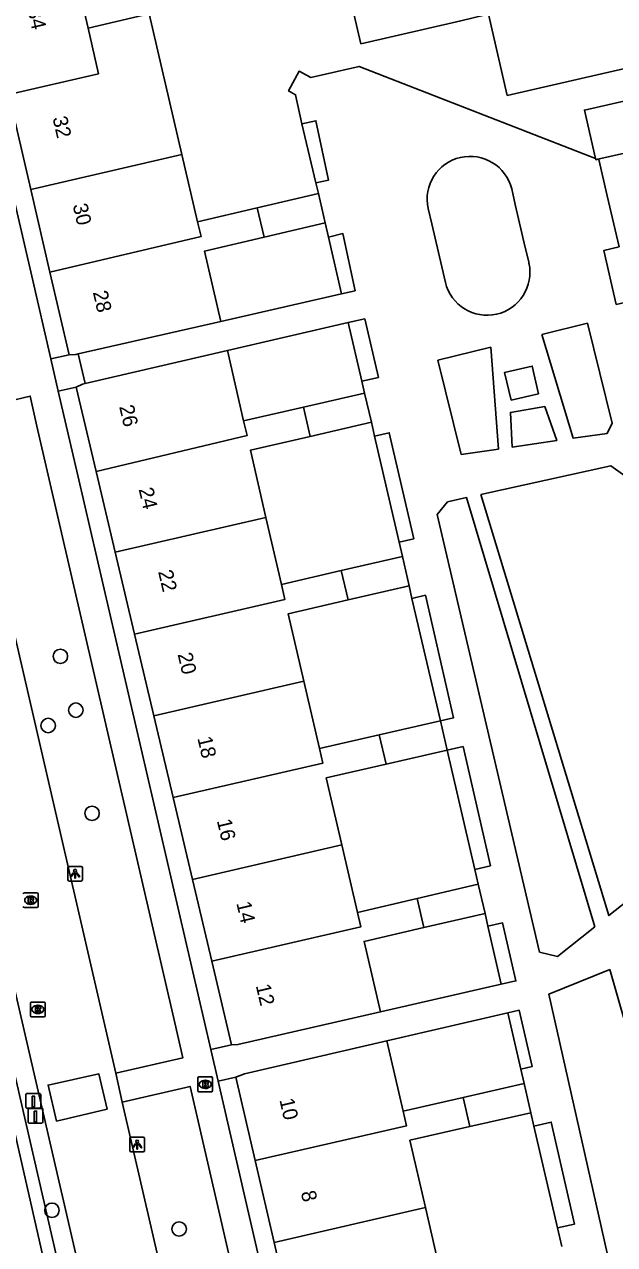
# Model space of a CAD drawing. Extents: x 156414 to 157775, y 382335 to 383765.
# Drawn here: x 156886.2 to 156926.2, y 383041 to 383123.7 of the extents above; entities that cross this region are included whole.
import ezdxf

# ---------------------------------------------------------------- set-up
doc = ezdxf.new("R2010")
doc.units = 0
for name, color, linetype in [('IMGEO_Berm_groen', 7, 'Continuous'), ('IMGEO_Boom', 7, 'Continuous'), ('IMGEO_Brandkraan', 7, 'Continuous'), ('IMGEO_Erf', 7, 'Continuous'), ('IMGEO_Greppel_droge_sloot', 7, 'Continuous'), ('IMGEO_Hek', 7, 'Continuous'), ('IMGEO_Lichtpunt', 7, 'Continuous'), ('IMGEO_Paal', 7, 'Continuous'), ('IMGEO_Pand', 7, 'Continuous'), ('IMGEO_Pand_nummerreeks', 7, 'Continuous'), ('IMGEO_Rijbaan_lokaal_gesloten', 7, 'Continuous'), ('IMGEO_Rijbaan_lokaal_open', 7, 'Continuous'), ('IMGEO_Rioolput', 7, 'Continuous'), ('IMGEO_Voetpad_open', 7, 'Continuous')]:
    doc.layers.add(name, color=color, linetype=linetype)

msp = doc.modelspace()

# ---------------------------------------------------------------- linework, layer by layer
at = {"layer": 'IMGEO_Berm_groen'}
msp.add_lwpolyline([(156881.029, 383072.193), (156889.957, 383033.371)], dxfattribs=at)
at = {"layer": 'IMGEO_Boom'}
for centre in [(156888.653, 383080.852), (156889.7, 383077.2), (156887.825, 383076.159), (156890.8, 383070.206), (156888.077, 383043.294), (156896.705, 383042.022)]:
    msp.add_circle(centre, 0.489, dxfattribs=at)
at = {"layer": 'IMGEO_Brandkraan'}
for p, q in [((156897.974, 383051.404), (156897.974, 383052.256)), ((156898.049, 383052.33), (156898.901, 383052.33)), ((156898.462, 383052.11), (156898.487, 383052.11)), ((156898.975, 383052.256), (156898.975, 383051.404)), ((156898.901, 383051.33), (156898.049, 383051.33)), ((156898.485, 383051.55), (156898.46, 383051.55))]:
    msp.add_line(p, q, dxfattribs=at)
for points in [[(156897.974, 383051.404), (156897.974, 383052.256)], [(156898.049, 383052.33), (156898.901, 383052.33)], [(156898.322, 383052.03), (156898.322, 383051.63), (156898.535, 383051.63)], [(156898.553, 383052.03), (156898.322, 383052.03)], [(156898.501, 383051.949), (156898.447, 383051.949), (156898.447, 383051.873)], [(156898.447, 383051.873), (156898.5, 383051.873)], [(156898.509, 383051.797), (156898.447, 383051.797), (156898.447, 383051.716)], [(156898.447, 383051.716), (156898.509, 383051.716)], [(156898.975, 383052.256), (156898.975, 383051.404)], [(156898.901, 383051.33), (156898.049, 383051.33)]]:
    msp.add_lwpolyline(points, dxfattribs=at)
for centre, radius, start, end in [((156898.051, 383052.254), 0.0765, 91.55205, 178.44795), ((156898.051, 383052.254), 0.0765, 91.55205, 178.44795), ((156898.502, 383051.911), 0.0379, 267.82845, 90.93552), ((156898.51, 383051.756), 0.0404, 269.87594, 90.50774), ((156898.541, 383051.881), 0.251, 268.66757, 293.53466), ((156898.557, 383051.885), 0.145, 59.4692, 91.53667), ((156898.582, 383051.932), 0.0922, 285.51372, 58.15012), ((156898.587, 383051.74), 0.105, 301.31148, 78.98903), ((156898.899, 383052.254), 0.0765, 1.55205, 88.44795), ((156898.899, 383052.254), 0.0765, 1.55205, 88.44795), ((156898.051, 383051.406), 0.0765, 181.55205, 268.44795), ((156898.051, 383051.406), 0.0765, 181.55205, 268.44795), ((156898.899, 383051.406), 0.0765, 271.55205, 358.44795), ((156898.899, 383051.406), 0.0765, 271.55205, 358.44795)]:
    msp.add_arc(centre, radius, start, end, dxfattribs=at)
for centre, major_axis, ratio, start_param, end_param in [((156898.461, 383051.83), (-0.387, 0.002), 0.722429, 4.712389, 7.853982), ((156898.486, 383051.83), (-0.39, 0.002), 0.717154, 1.570796, 4.712389)]:
    msp.add_ellipse(centre, major_axis=major_axis, ratio=ratio, start_param=start_param, end_param=end_param, dxfattribs=at)
at = {"layer": 'IMGEO_Erf'}
for points in [[(156905.981, 383112.959), (156905.026, 383116.964)], [(156907.714, 383105.431), (156906.834, 383109.282)], [(156908.172, 383103.475), (156909.093, 383099.499)], [(156909.964, 383095.778), (156911.622, 383088.598)], [(156912.494, 383084.782), (156914.423, 383076.479)], [(156914.882, 383074.49), (156916.748, 383066.407)], [(156918.547, 383058.619), (156917.645, 383062.552)], [(156919.88, 383052.856), (156918.997, 383056.674)], [(156922.363, 383042.091), (156920.759, 383049)]]:
    msp.add_lwpolyline(points, dxfattribs=at)
at = {"layer": 'IMGEO_Greppel_droge_sloot'}
msp.add_lwpolyline([(156888.996, 383033.414), (156881.195, 383067.66), (156880.531, 383071.202)], dxfattribs=at)
at = {"layer": 'IMGEO_Hek'}
msp.add_lwpolyline([(156890.338, 383099.343), (156889.863, 383101.352)], dxfattribs=at)
at = {"layer": 'IMGEO_Lichtpunt'}
for p, q in [((156889.153, 383066.516), (156889.153, 383065.709)), ((156889.153, 383066.516), (156889.153, 383065.709)), ((156890.055, 383066.611), (156889.247, 383066.611)), ((156890.055, 383066.611), (156889.247, 383066.611)), ((156890.149, 383065.709), (156890.149, 383066.516)), ((156890.149, 383065.709), (156890.149, 383066.516)), ((156889.247, 383065.615), (156890.055, 383065.615)), ((156889.247, 383065.615), (156890.055, 383065.615)), ((156893.361, 383048.152), (156893.361, 383047.345)), ((156893.361, 383048.152), (156893.361, 383047.345)), ((156894.263, 383048.247), (156893.455, 383048.247)), ((156894.263, 383048.247), (156893.455, 383048.247)), ((156894.357, 383047.345), (156894.357, 383048.152)), ((156894.357, 383047.345), (156894.357, 383048.152)), ((156893.455, 383047.251), (156894.263, 383047.251)), ((156893.455, 383047.251), (156894.263, 383047.251))]:
    msp.add_line(p, q, dxfattribs=at)
for points in [[(156889.527, 383066.18), (156889.566, 383066.152), (156889.378, 383065.89), (156889.34, 383065.917), (156889.527, 383066.18)], [(156889.629, 383066.132), (156889.676, 383066.132), (156889.676, 383065.81), (156889.629, 383065.81), (156889.629, 383066.132)], [(156889.739, 383066.152), (156889.777, 383066.179), (156889.964, 383065.917), (156889.925, 383065.889), (156889.739, 383066.152)], [(156893.735, 383047.816), (156893.774, 383047.788), (156893.586, 383047.526), (156893.548, 383047.553), (156893.735, 383047.816)], [(156893.837, 383047.768), (156893.884, 383047.768), (156893.884, 383047.446), (156893.837, 383047.446), (156893.837, 383047.768)], [(156893.947, 383047.788), (156893.985, 383047.815), (156894.172, 383047.553), (156894.133, 383047.525), (156893.947, 383047.788)]]:
    msp.add_lwpolyline(points, dxfattribs=at)
for centre in [(156889.652, 383066.314), (156893.86, 383047.95)]:
    msp.add_circle(centre, 0.0994, dxfattribs=at)
for centre, start, end in [((156889.247, 383066.516), 90, 180), ((156889.247, 383066.516), 90, 180), ((156890.055, 383066.516), 0, 90), ((156890.055, 383066.516), 0, 90), ((156889.247, 383065.709), 180, 270), ((156889.247, 383065.709), 180, 270), ((156890.055, 383065.709), 270, 0), ((156890.055, 383065.709), 270, 360), ((156893.455, 383048.152), 90, 180), ((156893.455, 383048.152), 90, 180), ((156894.263, 383048.152), 0, 90), ((156894.263, 383048.152), 0, 90), ((156893.455, 383047.345), 180, 270), ((156893.455, 383047.345), 180, 270), ((156894.263, 383047.345), 270, 0), ((156894.263, 383047.345), 270, 360)]:
    msp.add_arc(centre, 0.0946, start, end, dxfattribs=at)
at = {"layer": 'IMGEO_Paal'}
for p, q in [((156886.316, 383051.134), (156886.316, 383050.293)), ((156886.316, 383051.134), (156886.316, 383050.293)), ((156887.232, 383051.218), (156886.391, 383051.218)), ((156887.232, 383051.218), (156886.391, 383051.218)), ((156887.316, 383050.302), (156887.316, 383051.143)), ((156887.316, 383050.302), (156887.316, 383051.143)), ((156886.4, 383050.218), (156887.241, 383050.218)), ((156886.4, 383050.218), (156887.241, 383050.218)), ((156886.466, 383050.118), (156886.466, 383049.277)), ((156886.466, 383050.118), (156886.466, 383049.277)), ((156887.382, 383050.202), (156886.541, 383050.202)), ((156887.382, 383050.202), (156886.541, 383050.202)), ((156887.466, 383049.286), (156887.466, 383050.127)), ((156887.466, 383049.286), (156887.466, 383050.127)), ((156886.55, 383049.202), (156887.391, 383049.202)), ((156886.55, 383049.202), (156887.391, 383049.202))]:
    msp.add_line(p, q, dxfattribs=at)
for points in [[(156886.731, 383051.031), (156886.891, 383051.031), (156886.891, 383050.298), (156886.731, 383050.298), (156886.731, 383051.031)], [(156886.881, 383050.015), (156887.041, 383050.015), (156887.041, 383049.282), (156886.881, 383049.282), (156886.881, 383050.015)]]:
    msp.add_lwpolyline(points, dxfattribs=at)
for centre, start, end in [((156886.394, 383051.14), 92.4484, 184.28452), ((156886.394, 383051.14), 92.4484, 184.28452), ((156887.238, 383051.14), 2.4484, 94.28452), ((156887.238, 383051.14), 2.4484, 94.28452), ((156886.394, 383050.296), 182.4484, 274.28452), ((156886.394, 383050.296), 182.4484, 274.28452), ((156886.544, 383050.124), 92.4484, 184.28452), ((156886.544, 383050.124), 92.4484, 184.28452), ((156887.238, 383050.296), 272.4484, 4.28452), ((156887.238, 383050.296), 272.4484, 4.28452), ((156887.388, 383050.124), 2.4484, 94.28452), ((156887.388, 383050.124), 2.4484, 94.28452), ((156886.544, 383049.28), 182.4484, 274.28452), ((156886.544, 383049.28), 182.4484, 274.28452), ((156887.388, 383049.28), 272.4484, 4.28452), ((156887.388, 383049.28), 272.4484, 4.28452)]:
    msp.add_arc(centre, 0.0779, start, end, dxfattribs=at)
at = {"layer": 'IMGEO_Pand'}
for points in [[(156889.705, 383127.024), (156890.534, 383123.434)], [(156917.68, 383124.383), (156917.485, 383124.338), (156915.806, 383123.95), (156909.031, 383122.383), (156907.959, 383126.979)], [(156890.534, 383123.434), (156894.678, 383124.407), (156896.896, 383114.869)], [(156927.628, 383120.863), (156927.433, 383120.818), (156925.35, 383120.341), (156918.959, 383118.878), (156917.68, 383124.383)], [(156890.534, 383123.434), (156891.247, 383120.346), (156885.16, 383118.934)], [(156886.647, 383112.508), (156885.16, 383118.934)], [(156925.109, 383114.549), (156928.42, 383115.306), (156927.649, 383118.678), (156924.191, 383117.887), (156924.939, 383114.615)], [(156896.896, 383114.869), (156886.647, 383112.508)], [(156896.896, 383114.869), (156897.957, 383110.305)], [(156925.109, 383114.549), (156924.962, 383114.515), (156924.939, 383114.615)], [(156887.947, 383106.897), (156886.647, 383112.508)], [(156902.006, 383111.262), (156906.147, 383112.24)], [(156906.147, 383112.24), (156906.605, 383110.252)], [(156919.256, 383112.538), (156919.496, 383111.483), (156920.178, 383108.566), (156920.431, 383107.498)], [(156897.957, 383110.305), (156902.006, 383111.262)], [(156902.006, 383111.262), (156902.467, 383109.275)], [(156914.76, 383106.205), (156914.525, 383107.251), (156913.843, 383110.175), (156913.593, 383111.224)], [(156887.947, 383106.897), (156898.188, 383109.312), (156897.957, 383110.305)], [(156906.605, 383110.252), (156902.467, 383109.275)], [(156902.467, 383109.275), (156898.418, 383108.319), (156899.525, 383103.56)], [(156889.242, 383101.302), (156887.947, 383106.897)], [(156899.525, 383103.56), (156889.863, 383101.352), (156889.701, 383101.315), (156889.242, 383101.302)], [(156889.729, 383099.109), (156890.146, 383099.298), (156890.338, 383099.343), (156899.977, 383101.576)], [(156899.977, 383101.576), (156901.08, 383096.813)], [(156891.078, 383093.391), (156889.729, 383099.109)], [(156905.134, 383097.748), (156909.28, 383098.705)], [(156909.28, 383098.705), (156909.747, 383096.72)], [(156901.08, 383096.813), (156905.134, 383097.748)], [(156905.593, 383095.761), (156905.134, 383097.748)], [(156901.08, 383096.813), (156901.31, 383095.819), (156891.078, 383093.391)], [(156909.747, 383096.72), (156905.593, 383095.761)], [(156905.593, 383095.761), (156901.54, 383094.826), (156902.595, 383090.267)], [(156892.372, 383087.909), (156891.078, 383093.391)], [(156892.372, 383087.909), (156902.595, 383090.267)], [(156902.595, 383090.267), (156903.646, 383085.728)], [(156893.68, 383082.363), (156892.372, 383087.909)], [(156907.7, 383086.661), (156911.846, 383087.615)], [(156911.846, 383087.615), (156912.299, 383085.629)], [(156903.646, 383085.728), (156907.7, 383086.661)], [(156908.16, 383084.675), (156907.7, 383086.661)], [(156903.646, 383085.728), (156903.88, 383084.715), (156893.68, 383082.363)], [(156912.299, 383085.629), (156908.16, 383084.675)], [(156908.16, 383084.675), (156904.106, 383083.741), (156905.166, 383079.163)], [(156894.989, 383076.818), (156893.68, 383082.363)], [(156894.989, 383076.818), (156905.166, 383079.163)], [(156905.166, 383079.163), (156906.223, 383074.595)], [(156896.297, 383071.275), (156894.989, 383076.818)], [(156910.277, 383075.526), (156914.423, 383076.479)], [(156914.423, 383076.479), (156914.882, 383074.49)], [(156906.223, 383074.595), (156910.277, 383075.526)], [(156910.738, 383073.539), (156910.277, 383075.526)], [(156896.297, 383071.275), (156906.451, 383073.611), (156906.223, 383074.595)], [(156914.882, 383074.49), (156910.738, 383073.539)], [(156910.738, 383073.539), (156906.683, 383072.608), (156907.736, 383068.059)], [(156897.605, 383065.73), (156896.297, 383071.275)], [(156907.736, 383068.059), (156897.605, 383065.73)], [(156907.736, 383068.059), (156908.793, 383063.491)], [(156898.914, 383060.185), (156897.605, 383065.73)], [(156912.845, 383064.432), (156916.985, 383065.393)], [(156916.985, 383065.393), (156917.447, 383063.413)], [(156908.793, 383063.491), (156912.845, 383064.432)], [(156913.303, 383062.458), (156912.845, 383064.432)], [(156898.914, 383060.185), (156909.021, 383062.507), (156908.793, 383063.491)], [(156917.447, 383063.413), (156913.303, 383062.458)], [(156913.303, 383062.458), (156909.249, 383061.524), (156910.356, 383056.741)], [(156900.251, 383054.516), (156898.914, 383060.185)], [(156910.356, 383056.741), (156900.691, 383054.525), (156900.251, 383054.516)], [(156900.554, 383052.324), (156901.131, 383052.549), (156910.799, 383054.779)], [(156910.799, 383054.779), (156911.901, 383050.011)], [(156901.867, 383046.658), (156900.554, 383052.324)], [(156915.967, 383050.936), (156920.103, 383051.877)], [(156920.103, 383051.877), (156920.554, 383049.898)], [(156911.901, 383050.011), (156915.967, 383050.936)], [(156916.422, 383048.964), (156915.967, 383050.936)], [(156911.901, 383050.011), (156912.128, 383049.028), (156901.867, 383046.658)], [(156920.554, 383049.898), (156916.422, 383048.964)], [(156916.422, 383048.964), (156912.355, 383048.045), (156913.412, 383043.472)], [(156903.156, 383041.098), (156901.867, 383046.658)], [(156913.412, 383043.472), (156903.156, 383041.098)], [(156913.412, 383043.472), (156914.463, 383038.927)], [(156904.442, 383035.547), (156903.156, 383041.098)]]:
    msp.add_lwpolyline(points, dxfattribs=at)
for centre, radius, start, end in [((156916.433, 383111.845), 2.907, 13.78737, 192.33926), ((156917.588, 383106.883), 2.908, 193.47354, 12.21446)]:
    msp.add_arc(centre, radius, start, end, dxfattribs=at)
at = {"layer": 'IMGEO_Rijbaan_lokaal_gesloten'}
for points in [[(156891.143, 383032.914), (156891.24, 383033.646), (156876.165, 383098.859), (156864.383, 383149.838)], [(156892.411, 383052.582), (156891.866, 383054.936), (156882.501, 383095.375), (156882.029, 383097.412)], [(156892.844, 383050.62), (156892.411, 383052.582)], [(156900.135, 383019.061), (156892.844, 383050.62)]]:
    msp.add_lwpolyline(points, dxfattribs=at)
at = {"layer": 'IMGEO_Rijbaan_lokaal_open'}
msp.add_lwpolyline([(156888.38, 383049.344), (156887.822, 383051.781), (156891.26, 383052.539), (156891.815, 383050.151), (156888.38, 383049.344)], dxfattribs=at)
at = {"layer": 'IMGEO_Rioolput'}
for p, q in [((156886.212, 383064.814), (156887.064, 383064.814)), ((156886.648, 383064.034), (156886.623, 383064.034)), ((156886.625, 383064.594), (156886.65, 383064.594)), ((156887.138, 383064.74), (156887.138, 383063.888)), ((156887.064, 383063.814), (156886.212, 383063.814)), ((156886.698, 383057.412), (156887.55, 383057.412)), ((156886.623, 383056.486), (156886.623, 383057.338)), ((156887.134, 383056.632), (156887.109, 383056.632)), ((156887.111, 383057.192), (156887.136, 383057.192)), ((156887.624, 383057.338), (156887.624, 383056.486)), ((156887.55, 383056.412), (156886.698, 383056.412))]:
    msp.add_line(p, q, dxfattribs=at)
for points in [[(156886.212, 383064.814), (156887.064, 383064.814)], [(156886.726, 383064.512), (156886.474, 383064.514), (156886.474, 383064.114)], [(156886.474, 383064.114), (156886.598, 383064.114), (156886.598, 383064.276), (156886.609, 383064.276)], [(156886.652, 383064.433), (156886.598, 383064.433), (156886.598, 383064.352)], [(156886.598, 383064.352), (156886.65, 383064.352)], [(156886.656, 383064.247), (156886.727, 383064.114), (156886.867, 383064.114), (156886.802, 383064.24)], [(156887.138, 383064.74), (156887.138, 383063.888)], [(156887.064, 383063.814), (156886.212, 383063.814)], [(156886.698, 383057.412), (156887.55, 383057.412)], [(156886.623, 383056.486), (156886.623, 383057.338)], [(156887.212, 383057.11), (156886.96, 383057.112), (156886.96, 383056.712)], [(156886.96, 383056.712), (156887.084, 383056.712), (156887.084, 383056.874), (156887.095, 383056.874)], [(156887.138, 383057.031), (156887.084, 383057.031), (156887.084, 383056.95)], [(156887.084, 383056.95), (156887.136, 383056.95)], [(156887.142, 383056.845), (156887.213, 383056.712), (156887.353, 383056.712), (156887.288, 383056.838)], [(156887.624, 383057.338), (156887.624, 383056.486)], [(156887.55, 383056.412), (156886.698, 383056.412)]]:
    msp.add_lwpolyline(points, dxfattribs=at)
for centre, radius, start, end in [((156886.214, 383064.738), 0.0765, 91.55205, 178.44795), ((156886.214, 383064.738), 0.0765, 91.55205, 178.44795), ((156887.062, 383064.738), 0.0765, 1.55205, 88.44795), ((156887.062, 383064.738), 0.0765, 1.55205, 88.44795), ((156886.608, 383064.223), 0.0533, 26.02933, 88.69889), ((156886.634, 383064.541), 0.19, 274.7715, 282.96867), ((156886.658, 383064.337), 0.0964, 77.00612, 93.18647), ((156886.672, 383064.394), 0.0378, 276.66336, 79.67722), ((156886.725, 383064.402), 0.109, 350.36119, 89.41601), ((156886.723, 383064.402), 0.112, 277.58423, 350.98172), ((156886.707, 383064.187), 0.108, 29.51342, 73.79051), ((156886.214, 383063.89), 0.0765, 181.55205, 268.44795), ((156886.214, 383063.89), 0.0765, 181.55205, 268.44795), ((156887.062, 383063.89), 0.0765, 271.55205, 358.44795), ((156887.062, 383063.89), 0.0765, 271.55205, 358.44795), ((156886.7, 383057.336), 0.0765, 91.55205, 178.44795), ((156886.7, 383057.336), 0.0765, 91.55205, 178.44795), ((156887.548, 383057.336), 0.0765, 1.55205, 88.44795), ((156887.548, 383057.336), 0.0765, 1.55205, 88.44795), ((156887.094, 383056.821), 0.0533, 26.02933, 88.69889), ((156887.12, 383057.139), 0.19, 274.7715, 282.96867), ((156887.144, 383056.935), 0.0964, 77.00612, 93.18647), ((156887.158, 383056.992), 0.0378, 276.66336, 79.67722), ((156887.211, 383057), 0.109, 350.36119, 89.41601), ((156887.209, 383057), 0.112, 277.58423, 350.98172), ((156887.193, 383056.785), 0.108, 29.51342, 73.79051), ((156886.7, 383056.488), 0.0765, 181.55205, 268.44795), ((156886.7, 383056.488), 0.0765, 181.55205, 268.44795), ((156887.548, 383056.488), 0.0765, 271.55205, 358.44795), ((156887.548, 383056.488), 0.0765, 271.55205, 358.44795)]:
    msp.add_arc(centre, radius, start, end, dxfattribs=at)
for centre, major_axis, ratio, start_param, end_param in [((156886.624, 383064.314), (-0.387, 0.002), 0.722429, 4.712389, 7.853982), ((156886.649, 383064.314), (-0.39, 0.002), 0.717154, 1.570796, 4.712389), ((156887.11, 383056.912), (-0.387, 0.002), 0.722429, 4.712389, 7.853982), ((156887.135, 383056.912), (-0.39, 0.002), 0.717154, 1.570796, 4.712389)]:
    msp.add_ellipse(centre, major_axis=major_axis, ratio=ratio, start_param=start_param, end_param=end_param, dxfattribs=at)
at = {"layer": 'IMGEO_Voetpad_open'}
for points in [[(156879.13, 383139.346), (156886.707, 383106.634), (156888.007, 383101.021)], [(156924.939, 383114.615), (156908.904, 383120.851), (156905.629, 383120.098), (156904.841, 383120.522), (156904.122, 383119.186), (156904.607, 383118.926), (156905.026, 383116.964)], [(156905.026, 383116.964), (156905.981, 383117.168), (156906.841, 383113.143), (156905.981, 383112.959)], [(156926.546, 383108.606), (156925.732, 383112.071), (156925.155, 383114.531), (156925.109, 383114.549)], [(156905.981, 383112.959), (156906.147, 383112.24)], [(156906.605, 383110.252), (156906.834, 383109.282)], [(156906.834, 383109.282), (156907.814, 383109.514), (156908.641, 383105.643), (156907.714, 383105.431)], [(156927.401, 383104.963), (156926.352, 383104.717), (156925.497, 383108.36), (156926.546, 383108.606)], [(156907.714, 383105.431), (156899.525, 383103.56)], [(156908.172, 383103.475), (156909.293, 383103.734), (156910.214, 383099.758), (156909.093, 383099.499)], [(156899.977, 383101.576), (156908.172, 383103.475)], [(156921.311, 383102.669), (156924.388, 383103.431), (156926.063, 383096.667), (156925.729, 383095.967), (156923.433, 383095.637), (156921.311, 383102.669)], [(156889.242, 383101.302), (156888.007, 383101.021)], [(156915.835, 383094.542), (156914.255, 383100.921), (156917.84, 383101.809), (156918.352, 383094.905), (156915.835, 383094.542)], [(156888.007, 383101.021), (156888.507, 383098.821)], [(156919.211, 383098.222), (156918.779, 383100.097), (156920.65, 383100.527), (156921.081, 383098.652), (156919.211, 383098.222)], [(156888.507, 383098.821), (156889.729, 383099.109)], [(156888.507, 383098.821), (156889.831, 383093.107), (156898.845, 383054.19)], [(156909.093, 383099.499), (156909.28, 383098.705)], [(156892.411, 383052.582), (156896.967, 383053.629), (156896.418, 383056.005), (156887.063, 383096.468), (156886.61, 383098.492), (156882.029, 383097.412)], [(156919.286, 383095.039), (156919.173, 383097.394), (156921.498, 383097.782), (156922.314, 383095.476), (156919.286, 383095.039)], [(156909.747, 383096.72), (156909.964, 383095.778)], [(156909.964, 383095.778), (156910.953, 383096.007), (156912.611, 383088.827), (156911.622, 383088.598)], [(156917.174, 383091.826), (156925.984, 383093.777), (156926.93, 383093.098), (156932.558, 383069.033), (156932.278, 383068.364), (156925.855, 383063.273), (156917.174, 383091.826)], [(156924.9, 383062.516), (156922.357, 383060.5), (156921.148, 383060.794), (156914.199, 383090.475), (156914.911, 383091.325), (156916.193, 383091.609), (156924.9, 383062.516)], [(156911.622, 383088.598), (156911.846, 383087.615)], [(156912.299, 383085.629), (156912.494, 383084.782)], [(156912.494, 383084.782), (156913.402, 383084.991), (156915.316, 383076.684), (156914.423, 383076.479)], [(156914.882, 383074.49), (156915.957, 383074.737), (156916.999, 383070.195), (156917.812, 383066.651), (156916.748, 383066.407)], [(156916.748, 383066.407), (156916.985, 383065.393)], [(156917.447, 383063.413), (156917.645, 383062.552)], [(156917.645, 383062.552), (156918.637, 383062.78), (156919.543, 383058.847), (156918.547, 383058.619)], [(156925.902, 383059.621), (156930.778, 383042.645), (156926.435, 383039.826), (156925.723, 383040.384), (156921.783, 383057.954), (156925.902, 383059.621)], [(156918.547, 383058.619), (156910.356, 383056.741)], [(156910.799, 383054.779), (156918.997, 383056.674)], [(156918.997, 383056.674), (156919.758, 383056.85), (156920.641, 383053.032), (156919.88, 383052.856)], [(156900.251, 383054.516), (156898.845, 383054.19)], [(156898.845, 383054.19), (156899.345, 383052.043)], [(156919.88, 383052.856), (156920.103, 383051.877)], [(156892.844, 383050.62), (156897.445, 383051.688), (156904.74, 383020.113), (156900.135, 383019.061)], [(156899.345, 383052.043), (156900.554, 383052.324)], [(156899.345, 383052.043), (156907.049, 383018.602)], [(156920.554, 383049.898), (156920.759, 383049)], [(156920.759, 383049), (156921.937, 383049.269), (156923.513, 383042.353), (156922.363, 383042.091)], [(156922.363, 383042.091), (156922.651, 383040.832)]]:
    msp.add_lwpolyline(points, dxfattribs=at)

# ---------------------------------------------------------------- texts
at = {"layer": 'IMGEO_Pand_nummerreeks'}
for s, rotation, p in [('34', 283.03541, (156886.409, 383124.715)), ('32', 283.03541, (156888.112, 383117.357)), ('30', 283.03541, (156889.48, 383111.446)), ('28', 283.03541, (156890.848, 383105.539)), ('26', 283.27732, (156892.632, 383097.782)), ('24', 283.27732, (156893.952, 383092.186)), ('22', 283.27732, (156895.272, 383086.593)), ('20', 283.27732, (156896.594, 383080.992)), ('18', 283.27732, (156897.935, 383075.307)), ('16', 283.27732, (156899.255, 383069.714)), ('14', 283.27732, (156900.576, 383064.118)), ('12', 283.27732, (156901.895, 383058.525)), ('10', 283.04736, (156903.499, 383050.781)), ('8', 283.04736, (156904.953, 383044.507))]:
    msp.add_text(s, height=1, rotation=rotation, dxfattribs=at).set_placement(p)

doc.saveas('drawing.dxf')
